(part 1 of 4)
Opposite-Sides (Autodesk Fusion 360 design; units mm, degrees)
parameter "FrameLength" = 640 comment "Fixed existing outer length"
parameter "FrameWidth" = 190 comment "Fixed existing outer width"
parameter "FrameHeight" = 110 comment "Fixed existing height"
parameter "PivotHeight" = 30 comment "Above frame center"
parameter "LeverTravel" = 116 comment "Stable endpoint to endpoint"
parameter "PrintClearance" = 0.3 comment "Prototype diametral running clearance"
base_mesh_feature "Base Mesh Feature"
ground "Pin1"
work_plane "WorkPlane1" AlongDistance -36 ExtraOffset 0
sketch "Replaceable journal body" plane through (-36, 0, 0) normal (1, 0, 0) x axis (0, 0, -1)
  circle C1 centre (-65, 0) radius 10.05
extrude "Extrude1" new body sketch "Replaceable journal body" along normal blind 12 bodies "P03 Left flanged journal bush"
work_plane "WorkPlane2" AlongDistance -37.2 ExtraOffset 0
sketch "Axial thrust flange" plane through (-37.2, 0, 0) normal (1, 0, 0) x axis (0, 0, -1)
  circle C1 centre (-65, 0) radius 12.75
extrude "Extrude2" add sketch "Axial thrust flange" along normal blind 1.2
work_plane "WorkPlane3" AlongDistance -38 ExtraOffset 0
sketch "Running journal bore" plane through (-38, 0, 0) normal (1, 0, 0) x axis (0, 0, -1)
  circle C1 centre (-65, 0) radius 6.15
extrude "Extrude3" cut sketch "Running journal bore" along normal blind 15
work_plane "WorkPlane1" AlongDistance 24 ExtraOffset 0
sketch "Replaceable journal body" plane through (24, 0, 0) normal (1, 0, 0) x axis (0, 0, -1)
  circle C1 centre (-65, 0) radius 10.05
extrude "Extrude1" new body sketch "Replaceable journal body" along normal blind 12 bodies "P04 Right flanged journal bush"
work_plane "WorkPlane2" AlongDistance 36 ExtraOffset 0
sketch "Axial thrust flange" plane through (36, 0, 0) normal (1, 0, 0) x axis (0, 0, -1)
  circle C1 centre (-65, 0) radius 12.75
extrude "Extrude2" add sketch "Axial thrust flange" along normal blind 1.2
work_plane "WorkPlane3" AlongDistance 23 ExtraOffset 0
sketch "Running journal bore" plane through (23, 0, 0) normal (1, 0, 0) x axis (0, 0, -1)
  circle C1 centre (-65, 0) radius 6.15
extrude "Extrude3" cut sketch "Running journal bore" along normal blind 15
work_plane "WorkPlane1" AlongDistance 0 ExtraOffset 0
sketch "Palm grip smooth contour" plane through (0, 0, 0) normal (1, 0, 0) x axis (0, 0, -1)
  curve K1 (-225, 0) -> (-165, 12)
  line L1 (-225, 0) -> (-165, 0)
  line L2 (-165, 12) -> (-165, 0)
revolve "Revolve1" sketch "Palm grip smooth contour" AlongAngle 360 bodies "P09 Grip insert half"
work_plane "WorkPlane2" AlongDistance 0 ExtraOffset 0
sketch "Split on print bed face" plane through (0, 0, 0) normal (1, 0, 0) x axis (0, 0, -1)
  line L1 (-160, 30) -> (-160, -30)
  line L2 (-230, 30) -> (-160, 30)
  line L3 (-230, -30) -> (-230, 30)
  line L4 (-160, -30) -> (-230, -30)
extrude "Extrude1" cut sketch "Split on print bed face" along normal blind 30
work_plane "WorkPlane3" AlongDistance -7.2 ExtraOffset 0
sketch "Keyed stem socket" plane through (-7.2, 0, 0) normal (1, 0, 0) x axis (0, 0, -1)
  line L1 (-164, 7.2) -> (-164, -7.2)
  line L2 (-196, 7.2) -> (-164, 7.2)
  line L3 (-196, -7.2) -> (-196, 7.2)
  line L4 (-164, -7.2) -> (-196, -7.2)
extrude "Extrude2" cut sketch "Keyed stem socket" along normal blind 14.4
work_plane "WorkPlane4" AlongDistance -13.9 ExtraOffset 0
sketch "M3 grip heat set" plane through (-13.9, 0, 0) normal (1, 0, 0) x axis (0, 0, -1)
  circle C1 centre (-180, 0) radius 2
extrude "Extrude3" cut sketch "M3 grip heat set" along normal blind 6.8
work_plane "WorkPlane5" AlongDistance -13.9 ExtraOffset 0
sketch "M3 grip heat set (1)" plane through (-13.9, 0, 0) normal (1, 0, 0) x axis (0, 0, -1)
  circle C1 centre (-190, 0) radius 2
extrude "Extrude4" cut sketch "M3 grip heat set (1)" along normal blind 6.8
work_plane "WorkPlane1" AlongDistance 0 ExtraOffset 0
sketch "Palm grip smooth contour" plane through (0, 0, 0) normal (1, 0, 0) x axis (0, 0, -1)
  curve K1 (-225, 0) -> (-165, 12)
  line L1 (-225, 0) -> (-165, 0)
  line L2 (-165, 12) -> (-165, 0)
revolve "Revolve1" sketch "Palm grip smooth contour" AlongAngle 360 bodies "P10 Grip screw half"
work_plane "WorkPlane2" AlongDistance -30 ExtraOffset 0
sketch "Split on print bed face" plane through (-30, 0, 0) normal (1, 0, 0) x axis (0, 0, -1)
  line L1 (-160, 30) -> (-160, -30)
  line L2 (-230, 30) -> (-160, 30)
  line L3 (-230, -30) -> (-230, 30)
  line L4 (-160, -30) -> (-230, -30)
extrude "Extrude1" cut sketch "Split on print bed face" along normal blind 30
work_plane "WorkPlane3" AlongDistance -7.2 ExtraOffset 0
sketch "Keyed stem socket" plane through (-7.2, 0, 0) normal (1, 0, 0) x axis (0, 0, -1)
  line L1 (-164, 7.2) -> (-164, -7.2)
  line L2 (-196, 7.2) -> (-164, 7.2)
  line L3 (-196, -7.2) -> (-196, 7.2)
  line L4 (-164, -7.2) -> (-196, -7.2)
extrude "Extrude2" cut sketch "Keyed stem socket" along normal blind 14.4
work_plane "WorkPlane4" AlongDistance -0.1 ExtraOffset 0
sketch "Grip screw bore" plane through (-0.1, 0, 0) normal (1, 0, 0) x axis (0, 0, -1)
  circle C1 centre (-180, 0) radius 1.7
extrude "Extrude3" cut sketch "Grip screw bore" along normal blind 26
work_plane "WorkPlane5" AlongDistance 12.5 ExtraOffset 0
sketch "Recessed grip screw head" plane through (12.5, 0, 0) normal (1, 0, 0) x axis (0, 0, -1)
  circle C1 centre (-180, 0) radius 3.1
extrude "Extrude4" cut sketch "Recessed grip screw head" along normal blind 14
work_plane "WorkPlane6" AlongDistance -0.1 ExtraOffset 0
sketch "Grip screw bore (1)" plane through (-0.1, 0, 0) normal (1, 0, 0) x axis (0, 0, -1)
  circle C1 centre (-190, 0) radius 1.7
extrude "Extrude5" cut sketch "Grip screw bore (1)" along normal blind 26
work_plane "WorkPlane7" AlongDistance 12.5 ExtraOffset 0
sketch "Recessed grip screw head (1)" plane through (12.5, 0, 0) normal (1, 0, 0) x axis (0, 0, -1)
  circle C1 centre (-190, 0) radius 3.1
extrude "Extrude6" cut sketch "Recessed grip screw head (1)" along normal blind 14
work_plane "WorkPlane1" AlongDistance 4 ExtraOffset 0
sketch "First strong flat cheek" plane through (4, 0, 0) normal (1, 0, 0) x axis (0, 0, -1)
  line L1 (-6, -5) -> (-6, -61)
  line L2 (-7, 0) -> (-6, -5)
  line L3 (-17, 0) -> (-7, 0)
  line L4 (-18, -5) -> (-17, 0)
  line L5 (-18, -61) -> (-18, -5)
  line L6 (-6, -61) -> (-18, -61)
extrude "Extrude1" new body sketch "First strong flat cheek" along normal blind 3 bodies "P11 Forked roller follower"
work_plane "WorkPlane2" AlongDistance 4 ExtraOffset 0
sketch "Spring tail bridge" plane through (4, 0, 0) normal (1, 0, 0) x axis (0, 0, -1)
  line L1 (-6, -49) -> (-6, -61)
  line L2 (-18, -49) -> (-6, -49)
  line L3 (-18, -61) -> (-18, -49)
  line L4 (-6, -61) -> (-18, -61)
extrude "Extrude2" add sketch "Spring tail bridge" along normal blind 16
work_plane "WorkPlane3" AlongDistance 17 ExtraOffset 0
sketch "Second supporting cheek" plane through (17, 0, 0) normal (1, 0, 0) x axis (0, 0, -1)
  line L1 (-6, -5) -> (-6, -61)
  line L2 (-7, 0) -> (-6, -5)
  line L3 (-17, 0) -> (-7, 0)
  line L4 (-18, -5) -> (-17, 0)
  line L5 (-18, -61) -> (-18, -5)
  line L6 (-6, -61) -> (-18, -61)
extrude "Extrude3" add sketch "Second supporting cheek" along normal blind 3
work_plane "WorkPlane4" AlongDistance 4 ExtraOffset 0
sketch "Rounded roller cheek" plane through (4, 0, 0) normal (1, 0, 0) x axis (0, 0, -1)
  circle C1 centre (-12, 0) radius 6
extrude "Extrude4" add sketch "Rounded roller cheek" along normal blind 3
work_plane "WorkPlane5" AlongDistance 17 ExtraOffset 0
sketch "Rounded roller cheek (1)" plane through (17, 0, 0) normal (1, 0, 0) x axis (0, 0, -1)
  circle C1 centre (-12, 0) radius 6
extrude "Extrude5" add sketch "Rounded roller cheek (1)" along normal blind 3
work_plane "WorkPlane6" AlongDistance 3.9 ExtraOffset 0
sketch "Smooth pivot sleeve bore" plane through (3.9, 0, 0) normal (1, 0, 0) x axis (0, 0, -1)
  circle C1 centre (-12, -35) radius 4.15
extrude "Extrude6" cut sketch "Smooth pivot sleeve bore" along normal blind 16.2
work_plane "WorkPlane7" AlongDistance 3.9 ExtraOffset 0
sketch "Roller axle holes" plane through (3.9, 0, 0) normal (1, 0, 0) x axis (0, 0, -1)
  circle C1 centre (-12, 0) radius 1.7
extrude "Extrude7" cut sketch "Roller axle holes" along normal blind 16.2
work_plane "WorkPlane8" AlongDistance 3.9 ExtraOffset 0
sketch "Roller M3 nut recess" plane through (3.9, 0, 0) normal (1, 0, 0) x axis (0, 0, -1)
  line L1 (-14.9, 1.6743) -> (-12, 3.3486)
  line L2 (-14.9, -1.6743) -> (-14.9, 1.6743)
  line L3 (-12, -3.3486) -> (-14.9, -1.6743)
  line L4 (-9.1, -1.6743) -> (-12, -3.3486)
  line L5 (-9.1, 1.6743) -> (-9.1, -1.6743)
  line L6 (-12, 3.3486) -> (-9.1, 1.6743)
extrude "Extrude8" cut sketch "Roller M3 nut recess" along normal blind 1.6
work_plane "WorkPlane9" AlongDistance 18 ExtraOffset 0
sketch "Spring tail locating pilot" plane through (0, 0, 18) normal (0, 0, 1) x axis (1, 0, 0)
  circle C1 centre (12, -55) radius 1.8
extrude "Extrude9" add sketch "Spring tail locating pilot" along normal blind 2
work_plane "WorkPlane1" AlongDistance 3.1 ExtraOffset 0
sketch "Roller axle M3 nut" plane through (3.1, 0, 0) normal (1, 0, 0) x axis (0, 0, -1)
  line L1 (-14.75, 1.5877) -> (-12, 3.1754)
  line L2 (-14.75, -1.5877) -> (-14.75, 1.5877)
  line L3 (-12, -3.1754) -> (-14.75, -1.5877)
  line L4 (-9.25, -1.5877) -> (-12, -3.1754)
  line L5 (-9.25, 1.5877) -> (-9.25, -1.5877)
  line L6 (-12, 3.1754) -> (-9.25, 1.5877)
extrude "Extrude1" new body sketch "Roller axle M3 nut" along normal blind 2.4 bodies "HARDWARE Roller axle M3 nut"
work_plane "WorkPlane2" AlongDistance 3 ExtraOffset 0
sketch "Thread envelope" plane through (3, 0, 0) normal (1, 0, 0) x axis (0, 0, -1)
  circle C1 centre (-12, 0) radius 1.5
extrude "Extrude2" cut sketch "Thread envelope" along normal blind 2.6
ground "Pin4"
ground "Pin5"
work_plane "WorkPlane6" AlongDistance -7.2 ExtraOffset 0
sketch "Upright socket roof 45 degrees" plane through (0, -7.2, 0) normal (0, 1, 0) x axis (1, 0, 0)
  line L1 (-7.2, -196) -> (0, -196)
  line L2 (0, -203.2) -> (-7.2, -196)
  line L3 (0, -196) -> (0, -203.2)
extrude "Extrude5" cut sketch "Upright socket roof 45 degrees" along normal blind 14.4
work_plane "WorkPlane8" AlongDistance -7.2 ExtraOffset 0
sketch "Upright socket roof 45 degrees" plane through (0, -7.2, 0) normal (0, 1, 0) x axis (1, 0, 0)
  line L1 (7.2, -196) -> (0, -196)
  line L2 (0, -203.2) -> (7.2, -196)
  line L3 (0, -196) -> (0, -203.2)
extrude "Extrude7" cut sketch "Upright socket roof 45 degrees" along normal blind 14.4
work_plane "WorkPlane9" AlongDistance 9 ExtraOffset 0
sketch "Recess for stocked M3x20 grip screw" plane through (9, 0, 0) normal (1, 0, 0) x axis (0, 0, -1)
  circle C1 centre (-180, 0) radius 3.1
extrude "Extrude8" cut sketch "Recess for stocked M3x20 grip screw" along normal blind 3.6
work_plane "WorkPlane1" AlongDistance -11 ExtraOffset 0
sketch "Grip M3x20 cap head 180" plane through (-11, 0, 0) normal (1, 0, 0) x axis (0, 0, -1)
  circle C1 centre (-180, 0) radius 1.5
extrude "Extrude1" new body sketch "Grip M3x20 cap head 180" along normal blind 20 bodies "HARDWARE Grip M3x20 cap head 180"
work_plane "WorkPlane2" AlongDistance 9 ExtraOffset 0
sketch "Button head" plane through (9, 0, 0) normal (1, 0, 0) x axis (0, 0, -1)
  circle C1 centre (-180, 0) radius 2.75
extrude "Extrude2" add sketch "Button head" along normal blind 3
work_plane "WorkPlane10" AlongDistance 9 ExtraOffset 0
sketch "Recess for stocked M3x20 grip screw (1)" plane through (9, 0, 0) normal (1, 0, 0) x axis (0, 0, -1)
  circle C1 centre (-190, 0) radius 3.1
extrude "Extrude9" cut sketch "Recess for stocked M3x20 grip screw (1)" along normal blind 3.6
work_plane "WorkPlane1" AlongDistance -11 ExtraOffset 0
sketch "Grip M3x20 cap head 190" plane through (-11, 0, 0) normal (1, 0, 0) x axis (0, 0, -1)
  circle C1 centre (-190, 0) radius 1.5
extrude "Extrude1" new body sketch "Grip M3x20 cap head 190" along normal blind 20 bodies "HARDWARE Grip M3x20 cap head 190"
work_plane "WorkPlane2" AlongDistance 9 ExtraOffset 0
sketch "Button head" plane through (9, 0, 0) normal (1, 0, 0) x axis (0, 0, -1)
  circle C1 centre (-190, 0) radius 2.75
extrude "Extrude2" add sketch "Button head" along normal blind 3
work_plane "WorkPlane10" AlongDistance 7 ExtraOffset 0
sketch "Bearing inner race support pad" plane through (7, 0, 0) normal (1, 0, 0) x axis (0, 0, -1)
  circle C1 centre (-12, 0) radius 2.4
extrude "Extrude10" add sketch "Bearing inner race support pad" along normal blind 1
work_plane "WorkPlane11" AlongDistance 6.9 ExtraOffset 0
sketch "Preserve roller screw clearance" plane through (6.9, 0, 0) normal (1, 0, 0) x axis (0, 0, -1)
  circle C1 centre (-12, 0) radius 1.7
extrude "Extrude11" cut sketch "Preserve roller screw clearance" along normal blind 1.2
work_plane "WorkPlane12" AlongDistance 16 ExtraOffset 0
sketch "Bearing inner race support pad (1)" plane through (16, 0, 0) normal (1, 0, 0) x axis (0, 0, -1)
  circle C1 centre (-12, 0) radius 2.4
extrude "Extrude12" add sketch "Bearing inner race support pad (1)" along normal blind 1
work_plane "WorkPlane13" AlongDistance 15.9 ExtraOffset 0
sketch "Preserve roller screw clearance (1)" plane through (15.9, 0, 0) normal (1, 0, 0) x axis (0, 0, -1)
  circle C1 centre (-12, 0) radius 1.7
extrude "Extrude13" cut sketch "Preserve roller screw clearance (1)" along normal blind 1.2
work_plane "WorkPlane1" AlongDistance 8 ExtraOffset 0
sketch "Stock 623ZZ envelope 3x10x4" plane through (8, 0, 0) normal (1, 0, 0) x axis (0, 0, -1)
  circle C1 centre (-12, 0) radius 5
extrude "Extrude1" new body sketch "Stock 623ZZ envelope 3x10x4" along normal blind 4 bodies "HARDWARE 623ZZ roller bearing at 8"
work_plane "WorkPlane2" AlongDistance 7.9 ExtraOffset 0
sketch "Bearing inner race bore" plane through (7.9, 0, 0) normal (1, 0, 0) x axis (0, 0, -1)
  circle C1 centre (-12, 0) radius 1.5
extrude "Extrude2" cut sketch "Bearing inner race bore" along normal blind 4.2
work_plane "WorkPlane1" AlongDistance 12 ExtraOffset 0
sketch "Stock 623ZZ envelope 3x10x4" plane through (12, 0, 0) normal (1, 0, 0) x axis (0, 0, -1)
  circle C1 centre (-12, 0) radius 5
extrude "Extrude1" new body sketch "Stock 623ZZ envelope 3x10x4" along normal blind 4 bodies "HARDWARE 623ZZ roller bearing at 12"
work_plane "WorkPlane2" AlongDistance 11.9 ExtraOffset 0
sketch "Bearing inner race bore" plane through (11.9, 0, 0) normal (1, 0, 0) x axis (0, 0, -1)
  circle C1 centre (-12, 0) radius 1.5
extrude "Extrude2" cut sketch "Bearing inner race bore" along normal blind 4.2
work_plane "WorkPlane1" AlongDistance 32 ExtraOffset 0
sketch "Short compression sleeve" plane through (0, 0, 32) normal (0, 0, 1) x axis (1, 0, 0)
  circle C1 centre (4, -55) radius 2.5
extrude "Extrude1" new body sketch "Short compression sleeve" along normal blind 6 bodies "P27 Printed guide sleeve 4"
work_plane "WorkPlane2" AlongDistance 31.9 ExtraOffset 0
sketch "Guide screw bore" plane through (0, 0, 31.9) normal (0, 0, 1) x axis (1, 0, 0)
  circle C1 centre (4, -55) radius 1.65
extrude "Extrude2" cut sketch "Guide screw bore" along normal blind 6.2
work_plane "WorkPlane1" AlongDistance 32 ExtraOffset 0
sketch "Cup guide M3x12 4" plane through (0, 0, 32) normal (0, 0, 1) x axis (1, 0, 0)
  circle C1 centre (4, -55) radius 1.5
extrude "Extrude1" new body sketch "Cup guide M3x12 4" along normal blind 12 bodies "HARDWARE Cup guide M3x12 4"
work_plane "WorkPlane2" AlongDistance 29 ExtraOffset 0
sketch "Button head" plane through (0, 0, 29) normal (0, 0, 1) x axis (1, 0, 0)
  circle C1 centre (4, -55) radius 2.75
extrude "Extrude2" add sketch "Button head" along normal blind 3
work_plane "WorkPlane1" AlongDistance 32 ExtraOffset 0
sketch "Short compression sleeve" plane through (0, 0, 32) normal (0, 0, 1) x axis (1, 0, 0)
  circle C1 centre (20, -55) radius 2.5
extrude "Extrude1" new body sketch "Short compression sleeve" along normal blind 6 bodies "P27 Printed guide sleeve 20"
work_plane "WorkPlane2" AlongDistance 31.9 ExtraOffset 0
sketch "Guide screw bore" plane through (0, 0, 31.9) normal (0, 0, 1) x axis (1, 0, 0)
  circle C1 centre (20, -55) radius 1.65
extrude "Extrude2" cut sketch "Guide screw bore" along normal blind 6.2
work_plane "WorkPlane1" AlongDistance 32 ExtraOffset 0
sketch "Cup guide M3x12 20" plane through (0, 0, 32) normal (0, 0, 1) x axis (1, 0, 0)
  circle C1 centre (20, -55) radius 1.5
extrude "Extrude1" new body sketch "Cup guide M3x12 20" along normal blind 12 bodies "HARDWARE Cup guide M3x12 20"
work_plane "WorkPlane2" AlongDistance 29 ExtraOffset 0
sketch "Button head" plane through (0, 0, 29) normal (0, 0, 1) x axis (1, 0, 0)
  circle C1 centre (20, -55) radius 2.75
extrude "Extrude2" add sketch "Button head" along normal blind 3
work_plane "WorkPlane1" AlongDistance 0.2 ExtraOffset 0
sketch "Wide stock spring seat" plane through (0.2, 0, 0) normal (1, 0, 0) x axis (0, 0, -1)
  line L1 (-35, -49) -> (-35, -61)
  line L2 (-37, -49) -> (-35, -49)
  line L3 (-37, -61) -> (-37, -49)
  line L4 (-35, -61) -> (-37, -61)
extrude "Extrude1" new body sketch "Wide stock spring seat" along normal blind 23.6 bodies "P14 Captive spring cup for 9 mm spring"
work_plane "WorkPlane2" AlongDistance 29 ExtraOffset 0
sketch "Provisional 6 mm spring pilot" plane through (0, 0, 29) normal (0, 0, 1) x axis (1, 0, 0)
  circle C1 centre (12, -55) radius 3
extrude "Extrude2" add sketch "Provisional 6 mm spring pilot" along normal blind 6
work_plane "WorkPlane3" AlongDistance 34.9 ExtraOffset 0
sketch "Printed guide running clearance" plane through (0, 0, 34.9) normal (0, 0, 1) x axis (1, 0, 0)
  circle C1 centre (4, -55) radius 2.7
extrude "Extrude3" cut sketch "Printed guide running clearance" along normal blind 2.2
work_plane "WorkPlane4" AlongDistance 34.9 ExtraOffset 0
sketch "Printed guide running clearance (1)" plane through (0, 0, 34.9) normal (0, 0, 1) x axis (1, 0, 0)
  circle C1 centre (20, -55) radius 2.7
extrude "Extrude4" cut sketch "Printed guide running clearance (1)" along normal blind 2.2
work_plane "WorkPlane1" AlongDistance 55 ExtraOffset 0
sketch "Preserve one mm additional compression limit" plane through (0, 0, 55) normal (0, 0, 1) x axis (1, 0, 0)
  circle C1 centre (12, -55) radius 3.2
extrude "Extrude1" new body sketch "Preserve one mm additional compression limit" along normal blind 2 bodies "P15 Recessed preload limit collar 1 mm"
work_plane "WorkPlane2" AlongDistance 54.9 ExtraOffset 0
sketch "M3 adjuster clearance" plane through (0, 0, 54.9) normal (0, 0, 1) x axis (1, 0, 0)
  circle C1 centre (12, -55) radius 1.7
extrude "Extrude2" cut sketch "M3 adjuster clearance" along normal blind 2.2
work_plane "WorkPlane1" AlongDistance 37 ExtraOffset 0
sketch "Preload M3x20 cap head" plane through (0, 0, 37) normal (0, 0, 1) x axis (1, 0, 0)
  circle C1 centre (12, -55) radius 1.5
extrude "Extrude1" new body sketch "Preload M3x20 cap head" along normal blind 20 bodies "HARDWARE Preload M3x20 cap head"
work_plane "WorkPlane2" AlongDistance 57 ExtraOffset 0
sketch "Button head" plane through (0, 0, 57) normal (0, 0, 1) x axis (1, 0, 0)
  circle C1 centre (12, -55) radius 2.75
extrude "Extrude2" add sketch "Button head" along normal blind 3
work_plane "WorkPlane1" AlongDistance 18 ExtraOffset 0
sketch "Provisional stock spring installed envelope" plane through (0, 0, 18) normal (0, 0, 1) x axis (1, 0, 0)
  circle C1 centre (12, -55) radius 4.5
extrude "Extrude1" new body sketch "Provisional stock spring installed envelope" along normal blind 17 bodies "REFERENCE Stock spring OD9 wire1 free20 - rate and solid height assumed"
work_plane "WorkPlane2" AlongDistance 17.9 ExtraOffset 0
sketch "Stock spring nominal ID7" plane through (0, 0, 17.9) normal (0, 0, 1) x axis (1, 0, 0)
  circle C1 centre (12, -55) radius 3.5
extrude "Extrude2" cut sketch "Stock spring nominal ID7" along normal blind 17.2
work_plane "WorkPlane14" AlongDistance 4 ExtraOffset 0
sketch "Reinforced roof over support-free pivot bore" plane through (4, 0, 0) normal (1, 0, 0) x axis (0, 0, -1)
  line L1 (-17.9, -29) -> (-17.9, -41)
  line L2 (-20, -29) -> (-17.9, -29)
  line L3 (-20, -41) -> (-20, -29)
  line L4 (-17.9, -41) -> (-20, -41)
extrude "Extrude14" add sketch "Reinforced roof over support-free pivot bore" along normal blind 3
work_plane "WorkPlane15" AlongDistance 4 ExtraOffset 0
sketch "Flat print foot below roller cheek" plane through (4, 0, 0) normal (1, 0, 0) x axis (0, 0, -1)
  line L1 (-6, 6) -> (-6, -6)
  line L2 (-12, 6) -> (-6, 6)
  line L3 (-12, -6) -> (-12, 6)
  line L4 (-6, -6) -> (-12, -6)
extrude "Extrude15" add sketch "Flat print foot below roller cheek" along normal blind 3
work_plane "WorkPlane16" AlongDistance 17 ExtraOffset 0
sketch "Reinforced roof over support-free pivot bore (1)" plane through (17, 0, 0) normal (1, 0, 0) x axis (0, 0, -1)
  line L1 (-17.9, -29) -> (-17.9, -41)
  line L2 (-20, -29) -> (-17.9, -29)
  line L3 (-20, -41) -> (-20, -29)
  line L4 (-17.9, -41) -> (-20, -41)
extrude "Extrude16" add sketch "Reinforced roof over support-free pivot bore (1)" along normal blind 3
work_plane "WorkPlane17" AlongDistance 17 ExtraOffset 0
sketch "Flat print foot below roller cheek (1)" plane through (17, 0, 0) normal (1, 0, 0) x axis (0, 0, -1)
  line L1 (-6, 6) -> (-6, -6)
  line L2 (-12, 6) -> (-6, 6)
  line L3 (-12, -6) -> (-12, 6)
  line L4 (-6, -6) -> (-12, -6)
extrude "Extrude17" add sketch "Flat print foot below roller cheek (1)" along normal blind 3
work_plane "WorkPlane18" AlongDistance 3.9 ExtraOffset 0
sketch "Follower horizontal bore 45 degree roof" plane through (3.9, 0, 0) normal (1, 0, 0) x axis (0, 0, -1)
  line L1 (-14.9345, -32.0655) -> (-14.9345, -37.9345)
  line L2 (-17.869, -35) -> (-14.9345, -32.0655)
  line L3 (-14.9345, -37.9345) -> (-17.869, -35)
extrude "Extrude18" cut sketch "Follower horizontal bore 45 degree roof" along normal blind 16.2
work_plane "WorkPlane19" AlongDistance 3.9 ExtraOffset 0
sketch "Follower horizontal bore 45 degree roof (1)" plane through (3.9, 0, 0) normal (1, 0, 0) x axis (0, 0, -1)
  line L1 (-13.2021, 1.2021) -> (-13.2021, -1.2021)
  line L2 (-14.4042, 0) -> (-13.2021, 1.2021)
  line L3 (-13.2021, -1.2021) -> (-14.4042, 0)
extrude "Extrude19" cut sketch "Follower horizontal bore 45 degree roof (1)" along normal blind 16.2
work_plane "WorkPlane11" AlongDistance 9 ExtraOffset 0
sketch "Upright grip head pocket roof" plane through (9, 0, 0) normal (1, 0, 0) x axis (0, 0, -1)
  line L1 (-182.192, -2.192) -> (-182.192, 2.192)
  line L2 (-184.3841, 0) -> (-182.192, -2.192)
  line L3 (-182.192, 2.192) -> (-184.3841, 0)
extrude "Extrude10" cut sketch "Upright grip head pocket roof" along normal blind 16
work_plane "WorkPlane12" AlongDistance 9 ExtraOffset 0
sketch "Upright grip head pocket roof (1)" plane through (9, 0, 0) normal (1, 0, 0) x axis (0, 0, -1)
  line L1 (-192.192, -2.192) -> (-192.192, 2.192)
  line L2 (-194.3841, 0) -> (-192.192, -2.192)
  line L3 (-192.192, 2.192) -> (-194.3841, 0)
extrude "Extrude11" cut sketch "Upright grip head pocket roof (1)" along normal blind 16
work_plane "WorkPlane1" AlongDistance 2 ExtraOffset 0
sketch "Cam M3x10 cap head -45" plane through (2, 0, 0) normal (1, 0, 0) x axis (0, 0, -1)
  circle C1 centre (-39.5442, 25.4558) radius 1.5
extrude "Extrude1" new body sketch "Cam M3x10 cap head -45" along normal blind 10 bodies "HARDWARE Cam M3x10 cap head -45"
work_plane "WorkPlane2" AlongDistance 12 ExtraOffset 0
sketch "Button head" plane through (12, 0, 0) normal (1, 0, 0) x axis (0, 0, -1)
  circle C1 centre (-39.5442, 25.4558) radius 2.75
extrude "Extrude2" add sketch "Button head" along normal blind 3
work_plane "WorkPlane1" AlongDistance 2 ExtraOffset 0
sketch "Cam M3x10 cap head 0" plane through (2, 0, 0) normal (1, 0, 0) x axis (0, 0, -1)
  circle C1 centre (-29, 0) radius 1.5
extrude "Extrude1" new body sketch "Cam M3x10 cap head 0" along normal blind 10 bodies "HARDWARE Cam M3x10 cap head 0"
work_plane "WorkPlane2" AlongDistance 12 ExtraOffset 0
sketch "Button head" plane through (12, 0, 0) normal (1, 0, 0) x axis (0, 0, -1)
  circle C1 centre (-29, 0) radius 2.75
extrude "Extrude2" add sketch "Button head" along normal blind 3
work_plane "WorkPlane1" AlongDistance 2 ExtraOffset 0
sketch "Cam M3x10 cap head 45" plane through (2, 0, 0) normal (1, 0, 0) x axis (0, 0, -1)
  circle C1 centre (-39.5442, -25.4558) radius 1.5
extrude "Extrude1" new body sketch "Cam M3x10 cap head 45" along normal blind 10 bodies "HARDWARE Cam M3x10 cap head 45"
work_plane "WorkPlane2" AlongDistance 12 ExtraOffset 0
sketch "Button head" plane through (12, 0, 0) normal (1, 0, 0) x axis (0, 0, -1)
  circle C1 centre (-39.5442, -25.4558) radius 2.75
extrude "Extrude2" add sketch "Button head" along normal blind 3
work_plane "WorkPlane1" AlongDistance 0 ExtraOffset 0
sketch "Roller axle M3x20 cap head" plane through (0, 0, 0) normal (1, 0, 0) x axis (0, 0, -1)
  circle C1 centre (-12, 0) radius 1.5
extrude "Extrude1" new body sketch "Roller axle M3x20 cap head" along normal blind 20 bodies "HARDWARE Roller axle M3x20 cap head"
work_plane "WorkPlane2" AlongDistance 20 ExtraOffset 0
sketch "Button head" plane through (20, 0, 0) normal (1, 0, 0) x axis (0, 0, -1)
  circle C1 centre (-12, 0) radius 2.75
extrude "Extrude2" add sketch "Button head" along normal blind 3
work_plane "WorkPlane20" AlongDistance 3.9 ExtraOffset 0
sketch "Restore axle bore after adding print feet" plane through (3.9, 0, 0) normal (1, 0, 0) x axis (0, 0, -1)
  circle C1 centre (-12, 0) radius 1.7
extrude "Extrude20" cut sketch "Restore axle bore after adding print feet" along normal blind 16.2
work_plane "WorkPlane21" AlongDistance 3.9 ExtraOffset 0
sketch "Restore nut installation recess after print foot" plane through (3.9, 0, 0) normal (1, 0, 0) x axis (0, 0, -1)
  line L1 (-14.9, 1.6743) -> (-12, 3.3486)
  line L2 (-14.9, -1.6743) -> (-14.9, 1.6743)
  line L3 (-12, -3.3486) -> (-14.9, -1.6743)
  line L4 (-9.1, -1.6743) -> (-12, -3.3486)
  line L5 (-9.1, 1.6743) -> (-9.1, -1.6743)
  line L6 (-12, 3.3486) -> (-9.1, 1.6743)
extrude "Extrude21" cut sketch "Restore nut installation recess after print foot" along normal blind 1.6
work_plane "WorkPlane3" AlongDistance 8 ExtraOffset 0
sketch "Retain one mm preload travel before head meets collar" plane through (8, 0, 0) normal (1, 0, 0) x axis (0, 0, -1)
  line L1 (-56, -51) -> (-56, -59)
  line L2 (-57.1, -51) -> (-56, -51)
  line L3 (-57.1, -59) -> (-57.1, -51)
  line L4 (-56, -59) -> (-57.1, -59)
extrude "Extrude3" cut sketch "Retain one mm preload travel before head meets collar" along normal blind 8
work_plane "WorkPlane22" AlongDistance -2.5 ExtraOffset 0
sketch "Support-free lower ramp under left inner-race pad" plane through (0, -2.5, 0) normal (0, 1, 0) x axis (1, 0, 0)
  line L1 (8.1, -9.5) -> (7, -9.5)
  line L2 (8.1, -10.7) -> (8.1, -9.5)
  line L3 (7, -9.6) -> (8.1, -10.7)
  line L4 (7, -9.5) -> (7, -9.6)
extrude "Extrude22" cut sketch "Support-free lower ramp under left inner-race pad" along normal blind 5
work_plane "WorkPlane23" AlongDistance -2.5 ExtraOffset 0
sketch "Support-free lower ramp under right inner-race pad" plane through (0, -2.5, 0) normal (0, 1, 0) x axis (1, 0, 0)
  line L1 (17, -9.5) -> (15.9, -9.5)
  line L2 (17, -9.6) -> (17, -9.5)
  line L3 (15.9, -10.7) -> (17, -9.6)
  line L4 (15.9, -9.5) -> (15.9, -10.7)
extrude "Extrude23" cut sketch "Support-free lower ramp under right inner-race pad" along normal blind 5
ground "Pin106"
ground "Pin107"
ground "Pin108"
ground "Pin109"
ground "Pin110"
ground "Pin111"
ground "Pin112"
ground "Pin113"
work_plane "WorkPlane1" AlongDistance 40.5 ExtraOffset 0
sketch "Involute gear polygon m1.25 pressure20" plane through (40.5, 0, 0) normal (1, 0, 0) x axis (0, 0, -1)
  line L1 (-63.7058, 28.408) -> (-63.7058, 28.408)
  line L2 (-63.7507, 28.7619) -> (-63.7058, 28.408)
  line L3 (-63.8186, 29.1167) -> (-63.7507, 28.7619)
  line L4 (-63.9051, 29.4719) -> (-63.8186, 29.1167)
  line L5 (-64.0079, 29.8273) -> (-63.9051, 29.4719)
  line L6 (-64.1255, 30.1826) -> (-64.0079, 29.8273)
  line L7 (-64.257, 30.5378) -> (-64.1255, 30.1826)
  line L8 (-64.4015, 30.8926) -> (-64.257, 30.5378)
  line L9 (-64.5586, 31.2469) -> (-64.4015, 30.8926)
  line L10 (-65.4414, 31.2469) -> (-64.5586, 31.2469)
  line L11 (-65.5985, 30.8926) -> (-65.4414, 31.2469)
  line L12 (-65.743, 30.5378) -> (-65.5985, 30.8926)
  line L13 (-65.8745, 30.1826) -> (-65.743, 30.5378)
  line L14 (-65.9921, 29.8273) -> (-65.8745, 30.1826)
  line L15 (-66.0949, 29.4719) -> (-65.9921, 29.8273)
  line L16 (-66.1814, 29.1167) -> (-66.0949, 29.4719)
  line L17 (-66.2493, 28.7619) -> (-66.1814, 29.1167)
  line L18 (-66.2942, 28.408) -> (-66.2493, 28.7619)
  line L19 (-66.2942, 28.408) -> (-66.2942, 28.408)
  line L20 (-66.5771, 28.3937) -> (-66.2942, 28.408)
  line L21 (-66.8599, 28.3766) -> (-66.5771, 28.3937)
  line L22 (-67.1425, 28.3567) -> (-66.8599, 28.3766)
  line L23 (-67.4248, 28.3339) -> (-67.1425, 28.3567)
  line L24 (-67.4248, 28.3339) -> (-67.4248, 28.3339)
  line L25 (-67.5156, 28.6789) -> (-67.4248, 28.3339)
  line L26 (-67.6292, 29.0218) -> (-67.5156, 28.6789)
  line L27 (-67.7613, 29.3626) -> (-67.6292, 29.0218)
  line L28 (-67.9096, 29.7016) -> (-67.7613, 29.3626)
  line L29 (-68.0726, 30.0386) -> (-67.9096, 29.7016)
  line L30 (-68.2493, 30.3736) -> (-68.0726, 30.0386)
  line L31 (-68.4389, 30.7065) -> (-68.2493, 30.3736)
  line L32 (-68.6409, 31.0372) -> (-68.4389, 30.7065)
  line L33 (-69.5162, 30.9219) -> (-68.6409, 31.0372)
  line L34 (-69.6257, 30.5502) -> (-69.5162, 30.9219)
  line L35 (-69.7227, 30.1796) -> (-69.6257, 30.5502)
  line L36 (-69.8066, 29.8103) -> (-69.7227, 30.1796)
  line L37 (-69.8769, 29.4426) -> (-69.8066, 29.8103)
  line L38 (-69.9324, 29.0768) -> (-69.8769, 29.4426)
  line L39 (-69.9718, 28.7134) -> (-69.9324, 29.0768)
  line L40 (-69.9928, 28.3528) -> (-69.9718, 28.7134)
  line L41 (-69.9911, 27.9961) -> (-69.9928, 28.3528)
  line L42 (-69.9911, 27.9961) -> (-69.9911, 27.9961)
  line L43 (-70.2698, 27.945) -> (-69.9911, 27.9961)
  line L44 (-70.5479, 27.8911) -> (-70.2698, 27.945)
  line L45 (-70.8254, 27.8344) -> (-70.5479, 27.8911)
  line L46 (-71.1024, 27.775) -> (-70.8254, 27.8344)
  line L47 (-71.1024, 27.775) -> (-71.1024, 27.775)
  line L48 (-71.2374, 28.1052) -> (-71.1024, 27.775)
  line L49 (-71.3948, 28.4303) -> (-71.2374, 28.1052)
  line L50 (-71.5703, 28.751) -> (-71.3948, 28.4303)
  line L51 (-71.7616, 29.0677) -> (-71.5703, 28.751)
  line L52 (-71.9672, 29.3805) -> (-71.7616, 29.0677)
  line L53 (-72.1861, 29.6896) -> (-71.9672, 29.3805)
  line L54 (-72.4175, 29.9949) -> (-72.1861, 29.6896)
  line L55 (-72.6609, 30.2964) -> (-72.4175, 29.9949)
  line L56 (-73.5136, 30.0679) -> (-72.6609, 30.2964)
  line L57 (-73.5737, 29.6851) -> (-73.5136, 30.0679)
  line L58 (-73.6215, 29.305) -> (-73.5737, 29.6851)
  line L59 (-73.6565, 28.9279) -> (-73.6215, 29.305)
  line L60 (-73.6782, 28.5541) -> (-73.6565, 28.9279)
  line L61 (-73.6854, 28.1843) -> (-73.6782, 28.5541)
  line L62 (-73.6771, 27.8188) -> (-73.6854, 28.1843)
  line L63 (-73.6509, 27.4586) -> (-73.6771, 27.8188)
  line L64 (-73.6027, 27.1051) -> (-73.6509, 27.4586)
  line L65 (-73.6027, 27.1051) -> (-73.6027, 27.1051)
  line L66 (-73.8722, 27.018) -> (-73.6027, 27.1051)
  line L67 (-74.1409, 26.9283) -> (-73.8722, 27.018)
  line L68 (-74.4087, 26.8359) -> (-74.1409, 26.9283)
  line L69 (-74.6756, 26.7409) -> (-74.4087, 26.8359)
  line L70 (-74.6756, 26.7409) -> (-74.6756, 26.7409)
  line L71 (-74.8525, 27.0507) -> (-74.6756, 26.7409)
  line L72 (-75.051, 27.3524) -> (-74.8525, 27.0507)
  line L73 (-75.2669, 27.6474) -> (-75.051, 27.3524)
  line L74 (-75.4978, 27.9365) -> (-75.2669, 27.6474)
  line L75 (-75.7425, 28.2198) -> (-75.4978, 27.9365)
  line L76 (-75.9999, 28.4976) -> (-75.7425, 28.2198)
  line L77 (-76.2692, 28.7701) -> (-75.9999, 28.4976)
  line L78 (-76.5499, 29.0373) -> (-76.2692, 28.7701)
  line L79 (-77.3655, 28.6994) -> (-76.5499, 29.0373)
  line L80 (-77.375, 28.3121) -> (-77.3655, 28.6994)
  line L81 (-77.3728, 27.9289) -> (-77.375, 28.3121)
  line L82 (-77.3583, 27.5505) -> (-77.3728, 27.9289)
  line L83 (-77.331, 27.1771) -> (-77.3583, 27.5505)
  line L84 (-77.2899, 26.8095) -> (-77.331, 27.1771)
  line L85 (-77.2339, 26.4482) -> (-77.2899, 26.8095)
  line L86 (-77.1609, 26.0945) -> (-77.2339, 26.4482)
  line L87 (-77.067, 25.7503) -> (-77.1609, 26.0945)
  line L88 (-77.067, 25.7503) -> (-77.067, 25.7503)
  line L89 (-77.3229, 25.6288) -> (-77.067, 25.7503)
  line L90 (-77.5776, 25.5048) -> (-77.3229, 25.6288)
  line L91 (-77.831, 25.3783) -> (-77.5776, 25.5048)
  line L92 (-78.0832, 25.2492) -> (-77.831, 25.3783)
  line L93 (-78.0832, 25.2492) -> (-78.0832, 25.2492)
  line L94 (-78.299, 25.5332) -> (-78.0832, 25.2492)
  line L95 (-78.5352, 25.8065) -> (-78.299, 25.5332)
  line L96 (-78.7877, 26.0708) -> (-78.5352, 25.8065)
  line L97 (-79.0544, 26.3272) -> (-78.7877, 26.0708)
  line L98 (-79.334, 26.5762) -> (-79.0544, 26.3272)
  line L99 (-79.6254, 26.8181) -> (-79.334, 26.5762)
  line L100 (-79.928, 27.0531) -> (-79.6254, 26.8181)
  line L101 (-80.2412, 27.2813) -> (-79.928, 27.0531)
  line L102 (-81.0057, 26.8399) -> (-80.2412, 27.2813)
  line L103 (-80.9646, 26.4546) -> (-81.0057, 26.8399)
  line L104 (-80.9124, 26.075) -> (-80.9646, 26.4546)
  line L105 (-80.8487, 25.7017) -> (-80.9124, 26.075)
  line L106 (-80.7728, 25.3351) -> (-80.8487, 25.7017)
  line L107 (-80.6841, 24.9759) -> (-80.7728, 25.3351)
  line L108 (-80.5814, 24.6251) -> (-80.6841, 24.9759)
  line L109 (-80.4629, 24.2839) -> (-80.5814, 24.6251)
  line L110 (-80.3249, 23.955) -> (-80.4629, 24.2839)
  line L111 (-80.3249, 23.955) -> (-80.3249, 23.955)
  line L112 (-80.5627, 23.8011) -> (-80.3249, 23.955)
  line L113 (-80.799, 23.6449) -> (-80.5627, 23.8011)
  line L114 (-81.0338, 23.4864) -> (-80.799, 23.6449)
  line L115 (-81.2669, 23.3255) -> (-81.0338, 23.4864)
  line L116 (-81.2669, 23.3255) -> (-81.2669, 23.3255)
  line L117 (-81.518, 23.5789) -> (-81.2669, 23.3255)
  line L118 (-81.7879, 23.819) -> (-81.518, 23.5789)
  line L119 (-82.0727, 24.0481) -> (-81.7879, 23.819)
  line L120 (-82.3706, 24.2675) -> (-82.0727, 24.0481)
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extrude "Extrude1" new body sketch "Involute gear polygon m1.25 pressure20" along normal blind 8 bodies "G01R 48T gear with upper clamp"
work_plane "WorkPlane2" AlongDistance 40.4 ExtraOffset 0
sketch "Shaft bore" plane through (40.4, 0, 0) normal (1, 0, 0) x axis (0, 0, -1)
  circle C1 centre (-65, 0) radius 4.1
extrude "Extrude2" cut sketch "Shaft bore" along normal blind 8.2
work_plane "WorkPlane3" AlongDistance 40.5 ExtraOffset 0
sketch "D key flat" plane through (40.5, 0, 0) normal (1, 0, 0) x axis (0, 0, -1)
  line L1 (-62, 4.3) -> (-62, 3.35)
  line L2 (-68, 4.3) -> (-62, 4.3)
  line L3 (-68, 3.35) -> (-68, 4.3)
  line L4 (-62, 3.35) -> (-68, 3.35)
extrude "Extrude3" add sketch "D key flat" along normal blind 8
work_plane "WorkPlane4" AlongDistance 40.4 ExtraOffset 0
sketch "Clamp slit outside operating mesh sector" plane through (40.4, 0, 0) normal (1, 0, 0) x axis (0, 0, -1)
  line L1 (-32, 0.2) -> (-32, -0.2)
  line L2 (-65, 0.2) -> (-32, 0.2)
  line L3 (-65, -0.2) -> (-65, 0.2)
  line L4 (-32, -0.2) -> (-65, -0.2)
work_plane "WorkPlane5" AlongDistance -8 ExtraOffset 0
sketch "Clamp heat-set insert pocket" plane through (0, -8, 0) normal (0, 1, 0) x axis (1, 0, 0)
  circle C1 centre (44.5, -57) radius 2
work_plane "WorkPlane6" AlongDistance -1.3 ExtraOffset 0
sketch "Clamp through screw" plane through (0, -1.3, 0) normal (0, 1, 0) x axis (1, 0, 0)
  circle C1 centre (44.5, -57) radius 1.7
work_plane "WorkPlane7" AlongDistance 5 ExtraOffset 0
sketch "Recessed clamp screw head and tool path" plane through (0, 5, 0) normal (0, 1, 0) x axis (1, 0, 0)
  circle C1 centre (44.5, -57) radius 3.1
work_plane "WorkPlane1" AlongDistance 40.5 ExtraOffset 0
sketch "Involute gear polygon m1.25 pressure20" plane through (40.5, 0, 0) normal (1, 0, 0) x axis (0, 0, -1)
  line L1 (-110.8997, 14.0754) -> (-110.8647, 13.4185)
  line L2 (-110.9494, 14.3425) -> (-110.8997, 14.0754)
  line L3 (-111.0295, 14.6076) -> (-110.9494, 14.3425)
  line L4 (-111.1304, 14.8711) -> (-111.0295, 14.6076)
  line L5 (-111.2488, 15.1329) -> (-111.1304, 14.8711)
  line L6 (-111.383, 15.3927) -> (-111.2488, 15.1329)
  line L7 (-111.5317, 15.6505) -> (-111.383, 15.3927)
  line L8 (-111.6943, 15.9059) -> (-111.5317, 15.6505)
  line L9 (-111.87, 16.1587) -> (-111.6943, 15.9059)
  line L10 (-112.6708, 16.0533) -> (-111.87, 16.1587)
  line L11 (-112.7751, 15.7636) -> (-112.6708, 16.0533)
  line L12 (-112.866, 15.4748) -> (-112.7751, 15.7636)
  line L13 (-112.943, 15.1873) -> (-112.866, 15.4748)
  line L14 (-113.0053, 14.9016) -> (-112.943, 15.1873)
  line L15 (-113.0519, 14.6181) -> (-113.0053, 14.9016)
  line L16 (-113.0812, 14.3375) -> (-113.0519, 14.6181)
  line L17 (-113.0899, 14.0607) -> (-113.0812, 14.3375)
  line L18 (-113.0688, 13.7899) -> (-113.0899, 14.0607)
  line L19 (-112.9326, 13.1462) -> (-113.0688, 13.7899)
  line L20 (-113.2814, 13.0676) -> (-112.9326, 13.1462)
  line L21 (-113.6279, 12.9796) -> (-113.2814, 13.0676)
  line L22 (-113.9719, 12.8825) -> (-113.6279, 12.9796)
  line L23 (-114.3133, 12.7763) -> (-113.9719, 12.8825)
  line L24 (-114.5171, 13.4018) -> (-114.3133, 12.7763)
  line L25 (-114.6343, 13.6468) -> (-114.5171, 13.4018)
  line L26 (-114.7803, 13.8822) -> (-114.6343, 13.6468)
  line L27 (-114.9459, 14.1106) -> (-114.7803, 13.8822)
  line L28 (-115.128, 14.3328) -> (-114.9459, 14.1106)
  line L29 (-115.3249, 14.5491) -> (-115.128, 14.3328)
  line L30 (-115.5353, 14.7596) -> (-115.3249, 14.5491)
  line L31 (-115.7584, 14.9642) -> (-115.5353, 14.7596)
  line L32 (-115.9936, 15.1629) -> (-115.7584, 14.9642)
  line L33 (-116.7398, 14.8539) -> (-115.9936, 15.1629)
  line L34 (-116.7656, 14.547) -> (-116.7398, 14.8539)
  line L35 (-116.7786, 14.2446) -> (-116.7656, 14.547)
  line L36 (-116.7786, 13.947) -> (-116.7786, 14.2446)
  line L37 (-116.7649, 13.6548) -> (-116.7786, 13.947)
  line L38 (-116.7365, 13.3689) -> (-116.7649, 13.6548)
  line L39 (-116.6921, 13.0903) -> (-116.7365, 13.3689)
  line L40 (-116.6289, 12.8206) -> (-116.6921, 13.0903)
  line L41 (-116.5385, 12.5645) -> (-116.6289, 12.8206)
  line L42 (-116.2403, 11.9781) -> (-116.5385, 12.5645)
  line L43 (-116.5568, 11.8118) -> (-116.2403, 11.9781)
  line L44 (-116.8688, 11.6372) -> (-116.5568, 11.8118)
  line L45 (-117.176, 11.4544) -> (-116.8688, 11.6372)
  line L46 (-117.4782, 11.2634) -> (-117.176, 11.4544)
  line L47 (-117.837, 11.8148) -> (-117.4782, 11.2634)
  line L48 (-118.0136, 12.0212) -> (-117.837, 11.8148)
  line L49 (-118.2155, 12.2108) -> (-118.0136, 12.0212)
  line L50 (-118.4346, 12.3885) -> (-118.2155, 12.2108)
  line L51 (-118.668, 12.556) -> (-118.4346, 12.3885)
  line L52 (-118.9141, 12.714) -> (-118.668, 12.556)
  line L53 (-119.1718, 12.8628) -> (-118.9141, 12.714)
  line L54 (-119.4403, 13.0028) -> (-119.1718, 12.8628)
  line L55 (-119.7189, 13.1339) -> (-119.4403, 13.0028)
  line L56 (-120.3597, 12.6422) -> (-119.7189, 13.1339)
  line L57 (-120.3052, 12.3391) -> (-120.3597, 12.6422)
  line L58 (-120.2395, 12.0436) -> (-120.3052, 12.3391)
  line L59 (-120.1625, 11.7561) -> (-120.2395, 12.0436)
  line L60 (-120.0736, 11.4775) -> (-120.1625, 11.7561)
  line L61 (-119.9722, 11.2087) -> (-120.0736, 11.4775)
  line L62 (-119.8572, 10.951) -> (-119.9722, 11.2087)
  line L63 (-119.7264, 10.7069) -> (-119.8572, 10.951)
  line L64 (-119.5727, 10.4829) -> (-119.7264, 10.7069)
  line L65 (-119.1329, 9.9937) -> (-119.5727, 10.4829)
  line L66 (-119.3956, 9.7512) -> (-119.1329, 9.9937)
  line L67 (-119.6517, 9.5017) -> (-119.3956, 9.7512)
  line L68 (-119.9012, 9.2456) -> (-119.6517, 9.5017)
  line L69 (-120.1437, 8.9829) -> (-119.9012, 9.2456)
  line L70 (-120.6329, 9.4227) -> (-120.1437, 8.9829)
  line L71 (-120.8569, 9.5764) -> (-120.6329, 9.4227)
  line L72 (-121.101, 9.7072) -> (-120.8569, 9.5764)
  line L73 (-121.3587, 9.8222) -> (-121.101, 9.7072)
  line L74 (-121.6275, 9.9236) -> (-121.3587, 9.8222)
  line L75 (-121.9061, 10.0125) -> (-121.6275, 9.9236)
  line L76 (-122.1936, 10.0895) -> (-121.9061, 10.0125)
  line L77 (-122.4891, 10.1552) -> (-122.1936, 10.0895)
  line L78 (-122.7922, 10.2097) -> (-122.4891, 10.1552)
  line L79 (-123.2839, 9.5689) -> (-122.7922, 10.2097)
  line L80 (-123.1528, 9.2903) -> (-123.2839, 9.5689)
  line L81 (-123.0128, 9.0218) -> (-123.1528, 9.2903)
  line L82 (-122.864, 8.7641) -> (-123.0128, 9.0218)
  line L83 (-122.706, 8.518) -> (-122.864, 8.7641)
  line L84 (-122.5385, 8.2846) -> (-122.706, 8.518)
  line L85 (-122.3608, 8.0655) -> (-122.5385, 8.2846)
  line L86 (-122.1712, 7.8636) -> (-122.3608, 8.0655)
  line L87 (-121.9648, 7.687) -> (-122.1712, 7.8636)
  line L88 (-121.4134, 7.3282) -> (-121.9648, 7.687)
  line L89 (-121.6044, 7.026) -> (-121.4134, 7.3282)
  line L90 (-121.7872, 6.7187) -> (-121.6044, 7.026)
  line L91 (-121.9618, 6.4068) -> (-121.7872, 6.7187)
  line L92 (-122.1281, 6.0903) -> (-121.9618, 6.4068)
  line L93 (-122.7145, 6.3885) -> (-122.1281, 6.0903)
  line L94 (-122.9706, 6.4789) -> (-122.7145, 6.3885)
  line L95 (-123.2403, 6.5421) -> (-122.9706, 6.4789)
  line L96 (-123.5189, 6.5865) -> (-123.2403, 6.5421)
  line L97 (-123.8048, 6.6149) -> (-123.5189, 6.5865)
  line L98 (-124.097, 6.6286) -> (-123.8048, 6.6149)
  line L99 (-124.3946, 6.6286) -> (-124.097, 6.6286)
  line L100 (-124.697, 6.6156) -> (-124.3946, 6.6286)
  line L101 (-125.0039, 6.5898) -> (-124.697, 6.6156)
  line L102 (-125.3129, 5.8436) -> (-125.0039, 6.5898)
  line L103 (-125.1142, 5.6084) -> (-125.3129, 5.8436)
  line L104 (-124.9096, 5.3853) -> (-125.1142, 5.6084)
  line L105 (-124.6991, 5.1749) -> (-124.9096, 5.3853)
  line L106 (-124.4828, 4.978) -> (-124.6991, 5.1749)
  line L107 (-124.2606, 4.7959) -> (-124.4828, 4.978)
  line L108 (-124.0322, 4.6303) -> (-124.2606, 4.7959)
  line L109 (-123.7968, 4.4843) -> (-124.0322, 4.6303)
  line L110 (-123.5518, 4.3671) -> (-123.7968, 4.4843)
  line L111 (-122.9263, 4.1633) -> (-123.5518, 4.3671)
  line L112 (-123.0325, 3.8219) -> (-122.9263, 4.1633)
  line L113 (-123.1296, 3.4779) -> (-123.0325, 3.8219)
  line L114 (-123.2176, 3.1314) -> (-123.1296, 3.4779)
  line L115 (-123.2962, 2.7826) -> (-123.2176, 3.1314)
  line L116 (-123.9399, 2.9188) -> (-123.2962, 2.7826)
  line L117 (-124.2107, 2.9399) -> (-123.9399, 2.9188)
  line L118 (-124.4875, 2.9312) -> (-124.2107, 2.9399)
  line L119 (-124.7681, 2.9019) -> (-124.4875, 2.9312)
  line L120 (-125.0516, 2.8553) -> (-124.7681, 2.9019)
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extrude "Extrude1" new body sketch "Involute gear polygon m1.25 pressure20" along normal blind 8 bodies "G02 24T sensor pinion"
work_plane "WorkPlane2" AlongDistance 40.4 ExtraOffset 0
sketch "Shaft bore" plane through (40.4, 0, 0) normal (1, 0, 0) x axis (0, 0, -1)
  circle C1 centre (-110.15, 0) radius 3.1
extrude "Extrude2" cut sketch "Shaft bore" along normal blind 8.2
work_plane "WorkPlane3" AlongDistance 40.4 ExtraOffset 0
sketch "Sensor bushing end relief" plane through (40.4, 0, 0) normal (1, 0, 0) x axis (0, 0, -1)
  circle C1 centre (-110.15, 0) radius 3.6
extrude "Extrude3" cut sketch "Sensor bushing end relief" along normal blind 0.9
work_plane "WorkPlane4" AlongDistance 40.4 ExtraOffset 0
sketch "Clamp slit outside operating mesh sector" plane through (40.4, 0, 0) normal (1, 0, 0) x axis (0, 0, -1)
  line L1 (-110.15, 0.2) -> (-110.15, -0.2)
  line L2 (-127, 0.2) -> (-110.15, 0.2)
  line L3 (-127, -0.2) -> (-127, 0.2)
  line L4 (-110.15, -0.2) -> (-127, -0.2)
extrude "Extrude4" cut sketch "Clamp slit outside operating mesh sector" along normal blind 8.2
work_plane "WorkPlane5" AlongDistance -8 ExtraOffset 0
sketch "Clamp heat-set insert pocket" plane through (0, -8, 0) normal (0, 1, 0) x axis (1, 0, 0)
  circle C1 centre (44.5, -118.15) radius 2
work_plane "WorkPlane6" AlongDistance -1.3 ExtraOffset 0
sketch "Clamp through screw" plane through (0, -1.3, 0) normal (0, 1, 0) x axis (1, 0, 0)
  circle C1 centre (44.5, -118.15) radius 1.7
work_plane "WorkPlane7" AlongDistance 5 ExtraOffset 0
sketch "Recessed clamp screw head and tool path" plane through (0, 5, 0) normal (0, 1, 0) x axis (1, 0, 0)
  circle C1 centre (44.5, -118.15) radius 3.1
work_plane "WorkPlane1" AlongDistance 37 ExtraOffset 0
sketch "Geared RK097 supplied washer ASSUMED" plane through (37, 0, 0) normal (1, 0, 0) x axis (0, 0, -1)
  circle C1 centre (-110.15, 0) radius 6
extrude "Extrude1" new body sketch "Geared RK097 supplied washer ASSUMED" along normal blind 0.5 bodies "HARDWARE Geared RK097 supplied washer ASSUMED"
work_plane "WorkPlane2" AlongDistance 36.9 ExtraOffset 0
sketch "Washer clearance" plane through (36.9, 0, 0) normal (1, 0, 0) x axis (0, 0, -1)
  circle C1 centre (-110.15, 0) radius 3.6
extrude "Extrude2" cut sketch "Washer clearance" along normal blind 0.7
work_plane "WorkPlane1" AlongDistance 37.5 ExtraOffset 0
sketch "Geared RK097 supplied nut ASSUMED" plane through (37.5, 0, 0) normal (1, 0, 0) x axis (0, 0, -1)
  line L1 (-115.65, 3.1754) -> (-110.15, 6.3509)
  line L2 (-115.65, -3.1754) -> (-115.65, 3.1754)
  line L3 (-110.15, -6.3509) -> (-115.65, -3.1754)
  line L4 (-104.65, -3.1754) -> (-110.15, -6.3509)
  line L5 (-104.65, 3.1754) -> (-104.65, -3.1754)
  line L6 (-110.15, 6.3509) -> (-104.65, 3.1754)
extrude "Extrude1" new body sketch "Geared RK097 supplied nut ASSUMED" along normal blind 2 bodies "HARDWARE Geared RK097 supplied nut ASSUMED"
work_plane "WorkPlane2" AlongDistance 37.4 ExtraOffset 0
sketch "Thread envelope" plane through (37.4, 0, 0) normal (1, 0, 0) x axis (0, 0, -1)
  circle C1 centre (-110.15, 0) radius 3.5
extrude "Extrude2" cut sketch "Thread envelope" along normal blind 2.2
work_plane "WorkPlane8" AlongDistance -7 ExtraOffset 0
sketch "Revised clamp insert pocket" plane through (0, -7, 0) normal (0, 1, 0) x axis (1, 0, 0)
  circle C1 centre (44.5, -117.65) radius 2
extrude "Extrude8" cut sketch "Revised clamp insert pocket" along normal blind 6.8
work_plane "WorkPlane9" AlongDistance -0.3 ExtraOffset 0
sketch "Revised clamp screw clearance" plane through (0, -0.3, 0) normal (0, 1, 0) x axis (1, 0, 0)
  circle C1 centre (44.5, -117.65) radius 1.7
extrude "Extrude9" cut sketch "Revised clamp screw clearance" along normal blind 5.4
work_plane "WorkPlane10" AlongDistance 5 ExtraOffset 0
sketch "Revised recessed clamp head" plane through (0, 5, 0) normal (0, 1, 0) x axis (1, 0, 0)
  circle C1 centre (44.5, -117.65) radius 3.1
extrude "Extrude10" cut sketch "Revised recessed clamp head" along normal blind 30
work_plane "WorkPlane1" AlongDistance -7 ExtraOffset 0
sketch "G02 24T sensor pinion clamp M3x12" plane through (0, -7, 0) normal (0, 1, 0) x axis (1, 0, 0)
  circle C1 centre (44.5, -117.65) radius 1.5
extrude "Extrude1" new body sketch "G02 24T sensor pinion clamp M3x12" along normal blind 12 bodies "HARDWARE G02 24T sensor pinion clamp M3x12"
work_plane "WorkPlane2" AlongDistance 5 ExtraOffset 0
sketch "Button head" plane through (0, 5, 0) normal (0, 1, 0) x axis (1, 0, 0)
  circle C1 centre (44.5, -117.65) radius 2.75
extrude "Extrude2" add sketch "Button head" along normal blind 3
work_plane "WorkPlane11" AlongDistance 40.4 ExtraOffset 0
sketch "Open support-free clamp tool channel" plane through (40.4, 0, 0) normal (1, 0, 0) x axis (0, 0, -1)
  line L1 (-114.55, 18) -> (-114.55, 5)
  line L2 (-120.75, 18) -> (-114.55, 18)
  line L3 (-120.75, 5) -> (-120.75, 18)
  line L4 (-114.55, 5) -> (-120.75, 5)
extrude "Extrude11" cut sketch "Open support-free clamp tool channel" along normal blind 8.2
position "Position1"
work_plane "WorkPlane8" AlongDistance 40.4 ExtraOffset 0
sketch "Upper clamp split clear of lower mesh" plane through (40.4, 0, 0) normal (1, 0, 0) x axis (0, 0, -1)
  line L1 (-65, 0.2) -> (-65, -0.2)
  line L2 (-98, 0.2) -> (-65, 0.2)
  line L3 (-98, -0.2) -> (-98, 0.2)
  line L4 (-65, -0.2) -> (-98, -0.2)
extrude "Extrude8" cut sketch "Upper clamp split clear of lower mesh" along normal blind 8.2
work_plane "WorkPlane9" AlongDistance -8 ExtraOffset 0
sketch "Upper clamp insert" plane through (0, -8, 0) normal (0, 1, 0) x axis (1, 0, 0)
  circle C1 centre (44.5, -73) radius 2
extrude "Extrude9" cut sketch "Upper clamp insert" along normal blind 6.8
work_plane "WorkPlane10" AlongDistance -1.3 ExtraOffset 0
sketch "Upper clamp screw clearance" plane through (0, -1.3, 0) normal (0, 1, 0) x axis (1, 0, 0)
  circle C1 centre (44.5, -73) radius 1.7
extrude "Extrude10" cut sketch "Upper clamp screw clearance" along normal blind 6.4
work_plane "WorkPlane11" AlongDistance 5 ExtraOffset 0
sketch "Upper clamp head recess" plane through (0, 5, 0) normal (0, 1, 0) x axis (1, 0, 0)
  circle C1 centre (44.5, -73) radius 3.1
extrude "Extrude11" cut sketch "Upper clamp head recess" along normal blind 30
work_plane "WorkPlane1" AlongDistance -7 ExtraOffset 0
sketch "G01 upper clamp M3x12" plane through (0, -7, 0) normal (0, 1, 0) x axis (1, 0, 0)
  circle C1 centre (44.5, -73) radius 1.5
extrude "Extrude1" new body sketch "G01 upper clamp M3x12" along normal blind 12 bodies "HARDWARE G01 upper clamp M3x12"
work_plane "WorkPlane2" AlongDistance 5 ExtraOffset 0
sketch "Button head" plane through (0, 5, 0) normal (0, 1, 0) x axis (1, 0, 0)
  circle C1 centre (44.5, -73) radius 2.75
extrude "Extrude2" add sketch "Button head" along normal blind 3
ground "Unpin126"
ground "Unpin127"
ground "Unpin141"
ground "Unpin142"
ground "Unpin143"
ground "Unpin144"
ground "Unpin145"
ground "Unpin146"
ground "Unpin147"
ground "Unpin148"
position "Position2"
work_plane "WorkPlane1" AlongDistance 7 ExtraOffset 0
